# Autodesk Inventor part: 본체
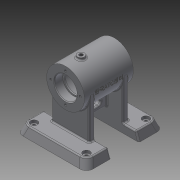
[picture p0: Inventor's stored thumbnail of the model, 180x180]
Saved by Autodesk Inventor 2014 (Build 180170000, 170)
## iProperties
Created: 2016-07
Part Number: 본체
Material: Generic
Document SubType Name: Modeling
Designer: Administrator
Density: 1 g/cm^3
Appearance: Default
Author: Administrator
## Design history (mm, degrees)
sketch "스케치1"
  geometry: C1 r 27 at (0, 70); 1 further point
  constraints: 1 centre point, 1 vertical alignment
  dimensions: "d0" = 54 diameter of C1; "d1" = 70 distance of C1.centre point (0, 0)
extrude "돌출1" new body sketch "스케치1" stored distance "d2" = 70; taper "d3" = 0 deg
hole "구멍1" diameter "d6" = 28; stored, may be unused: countersink angle "d10" = 90 deg, drill point angle "d12" = 0 deg; dims "d4" = 10, "d5" = 10, "d7" = 6, "d8" = 32, "d9" = 12, "d11" = 14
hole "구멍2" diameter "d15" = 28; stored, may be unused: countersink angle "d19" = 90 deg, drill point angle "d21" = 0 deg; dims "d13" = 10, "d14" = 10, "d16" = 6, "d17" = 32, "d18" = 12, "d20" = 14
node "작업 평면1"
sketch "스케치2"
  geometry: L1 (-27, -35)-(27, -35) reference; C1 r 5 at (0, -13); 1 further point
  constraints: 1 centre point, 1 vertical alignment
  dimensions: "d23" = 22 distance from line of C1.centre L1; "d24" = 10 diameter of C1
extrude "돌출2" join sketch "스케치2" stored distance "d25" = 70; taper "d26" = 0 deg
sketch "스케치3"
  geometry: C1 r 16 at (0, 0) reference; C2 r 27 at (0, 0) reference; A1 r 21 centre (0, 0) between (0, 21) and (21, 0); 3 further points
  constraints: 4 point on circle, 2 horizontal alignment, 2 vertical alignment, 1 centre point, 1 coincident
  dimensions: "d27" = 42 diameter of A1
hole "구멍3" sketch "스케치3" at (0, 21), (0, -21), (-21, 0), (21, 0) diameter "d28" = 3.242; stored, may be unused: countersink angle "d32" = 90 deg, drill point angle "d34" = 118 deg; dims "d29" = 8, "d30" = 32, "d31" = 12, "d33" = 10
hole "구멍4" diameter "d37" = 44; stored, may be unused: countersink angle "d41" = 90 deg, drill point angle "d43" = 0 deg; dims "d35" = 10, "d36" = 10, "d38" = 8, "d39" = 32, "d40" = 12, "d42" = 42
fillet "모깎기1" dims "d44" = 0.3
fillet "모깎기2" dims "d45" = 3
hole "구멍5" diameter "d48" = 5.188; stored, may be unused: countersink angle "d52" = 90 deg, drill point angle "d54" = 0 deg; dims "d46" = 10, "d47" = 10, "d49" = 20, "d50" = 32, "d51" = 12, "d53" = 42
fillet "모깎기3" dims "d55" = 2
node "작업 평면2"
sketch "스케치4"
  geometry: L1 (-35, 27)-(35, 27) reference; L2 (-35, 27)-(-35, -27) reference; 2 further points
  constraints: 1 other
  dimensions: "d56" = 70 distance of point (0, -70) point (0, 0); "d57" = 27 distance from line of point (0, 0) L1 (derived); "d58" = 35 distance from line of point (0, 0) L2
feature "엠보싱1" sketch "스케치4" dims "d0" = 54, "d59" = 0.5, "d60" = 0
sketch "스케치5"
  geometry: L1 (-50, -55)-(50, -55); L2 (50, -55)-(50, 55); L3 (50, 55)-(-50, 55); L4 (-50, 55)-(-50, -55); L5 (-50, -55)-(50, 55); L6 (50, -55)-(-50, 55); 1 further point
  constraints: 12 end point, 2 midpoint, 2 parallel, 1 horizontal, 1 perpendicular
  dimensions: "d61" = 100 distance of L3.end L2.end; "d62" = 110 distance of L2.end L1.end
extrude "돌출3" join sketch "스케치5" distance "d63" = 12; taper "d64" = -20 deg
sketch "스케치6"
  geometry: L1 (50, -20)-(-50, -20); L2 (-50, -20)-(-50, 20); L3 (-50, 20)-(50, 20); L4 (50, 20)-(50, -20); L5 (50, -20)-(-50, 20); L6 (-50, -20)-(50, 20); L7 (50, 55)-(-50, 55) reference; L8 (-50, -55)-(50, -55) reference; L9 (50, -55)-(50, 55) reference; L10 (-50, 55)-(-50, -55) reference; 3 further points
  constraints: 12 end point, 3 midpoint, 2 parallel, 1 coincident, 1 horizontal, 1 perpendicular
  dimensions: "d65" = 110 distance between parallel lines of L7 L8 (derived); "d66" = 100 distance between parallel lines of L9 L10 (derived); "d67" = 35 distance between parallel lines of L3 L7; "d68" = 100 distance of L2.end L3.end
extrude "돌출4" cut sketch "스케치6" distance "d69" = 12; taper "d70" = 0 deg
sketch "스케치7"
  geometry: L1 (45.632, -20)-(-45.632, -20) reference; L2 (-27, -20)-(27, -20); L3 (27, -20)-(27, -28); L4 (27, -28)-(-27, -28); L5 (-27, -28)-(-27, -20); 2 further points
  constraints: 8 end point, 2 parallel, 1 collinear, 1 horizontal, 1 midpoint, 1 perpendicular, 1 vertical alignment
  dimensions: "d71" = 8 distance between parallel lines of L4 L1; "d72" = 54 distance of L3.end L4.end
extrude "돌출5" join sketch "스케치7" stored distance "d73" = 12; taper "d74" = 0 deg
node "작업 평면3"
sketch "스케치8"
  geometry: L1 (-4, -20)-(4, -20); L2 (4, -20)-(4, 20); L3 (4, 20)-(-4, 20); L4 (-4, 20)-(-4, -20); L5 (-4, -20)-(4, 20); L6 (4, -20)-(-4, 20); L7 (50, 20)-(-50, 20) reference; 1 further point
  constraints: 12 end point, 2 midpoint, 2 parallel, 1 collinear, 1 horizontal, 1 perpendicular
  dimensions: "d76" = 8 distance between parallel lines of L2 L4
extrude "돌출6" join sketch "스케치8" stored distance "d77" = 12; taper "d78" = 0 deg
sketch "스케치9"
  geometry: L1 (50, 20)-(50, 55) reference; L2 (-50, 55)-(-50, 20) reference; L3 (-37.5, -42.5)-(37.5, -42.5); L4 (37.5, -42.5)-(37.5, 42.5); L5 (37.5, 42.5)-(-37.5, 42.5); L6 (-37.5, 42.5)-(-37.5, -42.5); L7 (-37.5, -42.5)-(37.5, 42.5); L8 (37.5, -42.5)-(-37.5, 42.5); 5 further points
  constraints: 12 end point, 4 coincident, 2 midpoint, 2 parallel, 1 horizontal, 1 perpendicular
  dimensions: "d79" = 100 distance between parallel lines of L1 L2 (derived); "d80" = 75 distance of L5.end L4.end; "d81" = 85 distance of L4.end L3.end
hole "구멍6" sketch "스케치9" at (-37.5, 42.5), (37.5, 42.5), (37.5, -42.5), (-37.5, -42.5) diameter "d82" = 6; stored, may be unused: countersink angle "d86" = 90 deg, drill point angle "d88" = 0 deg; dims "d83" = 20, "d84" = 10, "d85" = 4, "d87" = 42
fillet "모깎기4" dims "d89" = 10
fillet "모깎기5" dims "d90" = 2
fillet "모깎기6" dims "d91" = 2
fillet "모깎기7" dims "d92" = 2
sketch "스케치10"
  geometry: L1 (0, 36)-(0, 0) reference; L2 (-8, 10)-(-8, 26); L3 (-4.5, 10)-(-4.5, 26); L4 (-11.5, 26)-(-11.5, 10); L5 (24, 40)-(24, 63.603) reference; A1 r 3.5 centre (-8, 10) between (-11.5, 10) and (-4.5, 10); A2 r 3.5 centre (-8, 26) between (-4.5, 26) and (-11.5, 26); 2 further points
  constraints: 8 end point, 4 point on circle, 4 tangent, 2 centre point, 2 parallel, 1 horizontal alignment, 1 midpoint
  dimensions: "d93" = 32 distance between parallel lines of L2 L5; "d94" = 23 dimension on A2 A1; "d95" = 3.5 radius of A2
extrude "돌출7" cut sketch "스케치10" stored distance "d96" = 12; taper "d97" = 0 deg; dims "d36" = 10
fillet "모깎기8" dims "d98" = 2
sketch "스케치11"
  geometry: L1 (0, 70)-(15.898, 44.559); L2 (0, 70)-(0, 43); 2 further points
  constraints: 4 end point, 1 coincident, 1 vertical, 1 vertical alignment, 1 other
  dimensions: "d99" = 32 deg angle of L2 L1; "d100" = 30 distance of L1.start L1.end
node "작업 평면4"
sketch "스케치12"
  geometry: C1 r 6 at (0, 0); 2 further points
  constraints: 1 centre point, 1 coincident
  dimensions: "d101" = 12 diameter of C1
extrude "돌출8" join sketch "스케치12" stored distance "d102" = 12; taper "d103" = 0 deg
hole "구멍7" diameter "d106" = 5.188; stored, may be unused: countersink angle "d110" = 90 deg, drill point angle "d112" = 0 deg; dims "d104" = 10, "d105" = 10, "d107" = 30, "d108" = 10, "d109" = 4, "d111" = 30
fillet "모깎기9" dims "d113" = 2
chamfer "모따기1" distance "d114" = 1; stored, may be unused: second distance "d115" = 2, angle "d116" = 45 deg
node "솔리드1"
mirror "대칭1"
mirror "대칭2"
other parameters: "d75" = 22
